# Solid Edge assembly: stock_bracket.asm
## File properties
Author: Robert a Rhodes jr
Template: Normal.asm
Last saved by: TIET
Revision: 27
Application: Solid Edge
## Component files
adjusting_screw_guide.par
adjusting_nut_handle.par
stock_support_roller.par
Stock_support_base.par
thrust_bearing.par
adjusting_screw_nut.par
support_adjusting_screw.par
support_roller_bracket.par
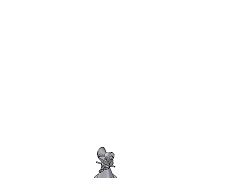
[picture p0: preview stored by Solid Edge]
